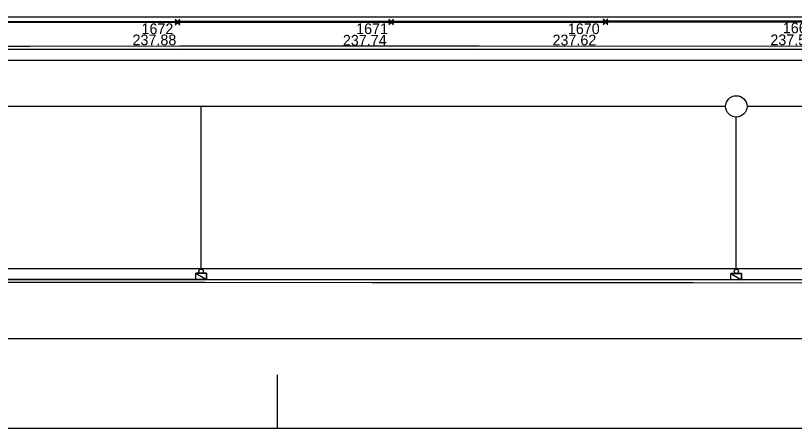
# Model space of a CAD drawing. Extents: x -264165 to -263733, y -1242319 to -1242245.
# Drawn here: x -263887.58 to -263851.2, y -1242319.19 to -1242299.91 of the extents above; entities that cross this region are included whole.
import ezdxf

# ---------------------------------------------------------------- set-up
doc = ezdxf.new("R2010")
doc.units = 0
for name, color, linetype in [('KFA_BOD_CISLO', 7, 'Continuous'), ('KFA_BOD_SYMBOL', 7, 'Continuous'), ('KFA_BOD_VYSKA', 7, 'Continuous'), ('KFA_SO_20-2_OBRUBNIKY_HORNA_HRANA', 7, 'Continuous'), ('PROJEKT_OBRUBNIKY_KOMUNIKACIE', 7, 'Continuous'), ('PROJEKT_TDZ_VODOROVNE', 7, 'Continuous'), ('RAM_NA_TLAC_1-250', 7, 'Continuous'), ('SITUACIA_DSP_2D', 7, 'Continuous'), ('SO_20-1_OBRUBNIKY_DOLNA_HRANA', 7, 'Continuous'), ('SO_20-1_OBRUBNIKY_HORNA_HRANA', 7, 'Continuous')]:
    doc.layers.add(name, color=color, linetype=linetype)

msp = doc.modelspace()

# ---------------------------------------------------------------- linework, layer by layer
at = {"layer": 'KFA_BOD_SYMBOL'}
for p, q in [((-263880.118, -1242300.298), (-263879.897, -1242300.076)), ((-263879.897, -1242300.298), (-263880.118, -1242300.076)), ((-263880.118, -1242300.347), (-263879.897, -1242300.127)), ((-263879.897, -1242300.347), (-263880.118, -1242300.127)), ((-263870.142, -1242300.291), (-263869.921, -1242300.069)), ((-263869.921, -1242300.291), (-263870.142, -1242300.069)), ((-263870.142, -1242300.34), (-263869.921, -1242300.12)), ((-263869.921, -1242300.34), (-263870.142, -1242300.12)), ((-263860.138, -1242300.285), (-263859.916, -1242300.063)), ((-263859.916, -1242300.285), (-263860.138, -1242300.063)), ((-263860.138, -1242300.335), (-263859.916, -1242300.113)), ((-263859.916, -1242300.335), (-263860.138, -1242300.113))]:
    msp.add_line(p, q, dxfattribs=at)
at = {"layer": 'KFA_SO_20-2_OBRUBNIKY_HORNA_HRANA'}
for points in [[(-263818.454, -1242300.127), (-263820.114, -1242300.153), (-263830.062, -1242300.171), (-263840.06, -1242300.171), (-263850.054, -1242300.16), (-263860.027, -1242300.174), (-263870.031, -1242300.18), (-263880.008, -1242300.187), (-263888.684, -1242300.195), (-263899.013, -1242300.19), (-263908.987, -1242300.212), (-263915.978, -1242300.22), (-263917.721, -1242300.207)], [(-263818.504, -1242300.177), (-263820.112, -1242300.193), (-263830.062, -1242300.221), (-263840.06, -1242300.221), (-263850.054, -1242300.21), (-263860.027, -1242300.224), (-263870.031, -1242300.23), (-263880.008, -1242300.237), (-263888.684, -1242300.245), (-263899.013, -1242300.24), (-263908.987, -1242300.262), (-263915.978, -1242300.27), (-263917.654, -1242300.257)]]:
    msp.add_lwpolyline(points, dxfattribs=at)
at = {"layer": 'PROJEKT_OBRUBNIKY_KOMUNIKACIE'}
for p, q in [((-263816.308, -1242299.982), (-263918.049, -1242299.982)), ((-263914.08, -1242301.482), (-263815.822, -1242301.482)), ((-263842.601, -1242312.24), (-263924.192, -1242312.232)), ((-264038.443, -1242314.982), (-263836.403, -1242314.982))]:
    msp.add_line(p, q, dxfattribs=at)
at = {"layer": 'PROJEKT_TDZ_VODOROVNE'}
for p, q in [((-263913.857, -1242301.982), (-263816.374, -1242301.982)), ((-263842.661, -1242311.732), (-263980.94, -1242311.732))]:
    msp.add_line(p, q, dxfattribs=at)
at = {"layer": 'RAM_NA_TLAC_1-250'}
msp.add_line((-263875.363, -1242316.685), (-263875.363, -1242319.185), dxfattribs=at)
msp.add_lwpolyline([(-264165.363, -1242244.935), (-263732.863, -1242244.935), (-263732.863, -1242319.185), (-264165.363, -1242319.185)], close=True, dxfattribs=at)
at = {"layer": 'SITUACIA_DSP_2D'}
for p, q in [((-263816.308, -1242299.982), (-263918.049, -1242299.982)), ((-263914.08, -1242301.482), (-263815.822, -1242301.482)), ((-263854.415, -1242304.147), (-263903.413, -1242304.147)), ((-263878.913, -1242311.742), (-263878.913, -1242304.147)), ((-263809.091, -1242304.153), (-263853.415, -1242304.148)), ((-263853.915, -1242311.749), (-263853.915, -1242304.647)), ((-263879.163, -1242311.942), (-263878.663, -1242311.942)), ((-263879.163, -1242312.232), (-263879.163, -1242311.942)), ((-263879.163, -1242311.942), (-263878.663, -1242312.232)), ((-263879.163, -1242311.942), (-263878.663, -1242312.232)), ((-263878.663, -1242311.942), (-263879.163, -1242311.942)), ((-263878.663, -1242311.942), (-263878.663, -1242312.232)), ((-263878.663, -1242312.232), (-263878.663, -1242311.942)), ((-263854.165, -1242311.949), (-263853.665, -1242311.949)), ((-263854.165, -1242312.239), (-263854.165, -1242311.949)), ((-263854.165, -1242311.949), (-263853.665, -1242312.239)), ((-263854.165, -1242311.949), (-263853.665, -1242312.239)), ((-263853.665, -1242311.949), (-263854.165, -1242311.949)), ((-263853.665, -1242311.949), (-263853.665, -1242312.239)), ((-263853.665, -1242312.239), (-263853.665, -1242311.949)), ((-263980.94, -1242312.232), (-263857.327, -1242312.232)), ((-263842.601, -1242312.24), (-263924.192, -1242312.232)), ((-263878.663, -1242312.232), (-263879.163, -1242312.232)), ((-263853.665, -1242312.239), (-263854.165, -1242312.239)), ((-264038.443, -1242314.982), (-263836.403, -1242314.982))]:
    msp.add_line(p, q, dxfattribs=at)
for centre, radius in [((-263853.915, -1242304.147), 0.5), ((-263878.913, -1242311.842), 0.1), ((-263853.915, -1242311.849), 0.1)]:
    msp.add_circle(centre, radius, dxfattribs=at)
at = {"layer": 'SO_20-1_OBRUBNIKY_DOLNA_HRANA'}
for points in [[(-263913.884, -1242301.489), (-263907.893, -1242301.489), (-263900.89, -1242301.488), (-263893.898, -1242301.483), (-263886.917, -1242301.473), (-263879.922, -1242301.465), (-263872.91, -1242301.469), (-263865.929, -1242301.465), (-263859.932, -1242301.473), (-263850.941, -1242301.471), (-263843.947, -1242301.471), (-263836.942, -1242301.481), (-263829.943, -1242301.484), (-263823.945, -1242301.487), (-263818.452, -1242301.495), (-263816.42, -1242301.504)], [(-263927.909, -1242312.235), (-263920.91, -1242312.234), (-263913.915, -1242312.225), (-263906.912, -1242312.227), (-263898.896, -1242312.208), (-263891.9, -1242312.209), (-263883.905, -1242312.21), (-263878.731, -1242312.212), (-263870.923, -1242312.226), (-263863.907, -1242312.232), (-263855.93, -1242312.232)], [(-263855.93, -1242312.232), (-263849.929, -1242312.239), (-263843.916, -1242312.251), (-263841.932, -1242312.261)]]:
    msp.add_lwpolyline(points, dxfattribs=at)
at = {"layer": 'SO_20-1_OBRUBNIKY_HORNA_HRANA'}
for points in [[(-263913.884, -1242301.344), (-263907.893, -1242301.343), (-263900.896, -1242301.344), (-263893.895, -1242301.338), (-263886.916, -1242301.328), (-263879.921, -1242301.324), (-263872.911, -1242301.324), (-263865.928, -1242301.325), (-263859.931, -1242301.327), (-263850.935, -1242301.324), (-263843.941, -1242301.331), (-263836.939, -1242301.332), (-263829.941, -1242301.342), (-263823.94, -1242301.343), (-263818.456, -1242301.352), (-263816.413, -1242301.358)], [(-263927.907, -1242312.381), (-263920.909, -1242312.378), (-263913.91, -1242312.365), (-263906.907, -1242312.358), (-263898.91, -1242312.357), (-263891.902, -1242312.354), (-263883.907, -1242312.356), (-263878.731, -1242312.358), (-263870.924, -1242312.368), (-263863.913, -1242312.368), (-263855.926, -1242312.378)], [(-263855.926, -1242312.378), (-263849.928, -1242312.38), (-263843.916, -1242312.392), (-263841.931, -1242312.403)]]:
    msp.add_lwpolyline(points, dxfattribs=at)

# ---------------------------------------------------------------- texts
at = {"layer": 'KFA_BOD_CISLO'}
for s, p in [('1672', (-263881.694, -1242300.773)), ('1671', (-263871.67, -1242300.769)), ('1670', (-263861.782, -1242300.769)), ('1669', (-263851.743, -1242300.732))]:
    msp.add_text(s, height=0.5, dxfattribs=at).set_placement(p)
at = {"layer": 'KFA_BOD_VYSKA'}
for s, p in [('237.88', (-263882.113, -1242301.291)), ('237.74', (-263872.29, -1242301.308)), ('237.62', (-263862.499, -1242301.297)), ('237.50', (-263852.325, -1242301.289))]:
    msp.add_text(s, height=0.5, dxfattribs=at).set_placement(p)

doc.saveas('drawing.dxf')
